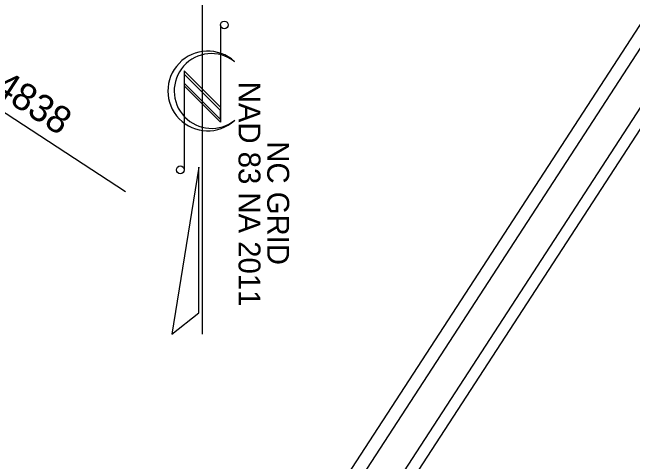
# Model space of a CAD drawing. Extents: x 2291197 to 2302790, y 592892 to 604246.
# Drawn here: x 2300199 to 2301153, y 599026 to 599716 of the extents above; entities that cross this region are included whole.
import ezdxf

# ---------------------------------------------------------------- set-up
doc = ezdxf.new("R2010")
doc.units = 0
for name, color, linetype in [('Prop Horizontal Alignment Station Label', 7, 'Continuous'), ('Sheet North Arrow CELL', 7, 'Continuous'), ('Sheet Plot Border Inside CELL', 7, 'Continuous'), ('Sheet Plot Border Outside CELL', 7, 'Continuous'), ('Sheet Title CELL', 7, 'Continuous')]:
    doc.layers.add(name, color=color, linetype=linetype)

msp = doc.modelspace()

# ---------------------------------------------------------------- linework, layer by layer
at = {"layer": 'Prop Horizontal Alignment Station Label'}
msp.add_line((2299671.29, 599897.36), (2300373.21, 599441.07), dxfattribs=at)
at = {"layer": 'Sheet North Arrow CELL'}
for p, q in [((2300491.59, 599221.54), (2300491.59, 599950.84)), ((2300519.07, 599697.05), (2300519.07, 599547.37)), ((2300539.72, 599641.28), (2300540.5, 599640.72)), ((2300519.07, 599570.71), (2300463.31, 599626.47)), ((2300463.31, 599626.47), (2300463.31, 599474.33)), ((2300519.07, 599565.21), (2300463.31, 599620.97)), ((2300463.31, 599620.97), (2300463.31, 599607.29)), ((2300519.07, 599551.52), (2300463.31, 599607.29)), ((2300463.31, 599607.29), (2300519.07, 599551.52)), ((2300519.07, 599547.37), (2300463.31, 599603.13)), ((2300519.07, 599551.52), (2300519.07, 599565.21))]:
    msp.add_line(p, q, dxfattribs=at)
msp.add_lwpolyline([(2300485.64, 599478.48), (2300444.35, 599221.54), (2300485.64, 599254.08)], close=True, dxfattribs=at)
for centre in [(2300525.02, 599696.93), (2300457.37, 599474.1)]:
    msp.add_circle(centre, 5.95, dxfattribs=at)
for centre, radius, start, end in [((2300499.34, 599595.31), 61.26, 47.84002, 312.39406), ((2300505.26, 599595.34), 57.43, 53.09504, 308.62871)]:
    msp.add_arc(centre, radius, start, end, dxfattribs=at)
at = {"layer": 'Sheet Plot Border Inside CELL'}
msp.add_lwpolyline([(2293886.07, 600604.03), (2299474.98, 596970.9), (2301775.2, 600509.37), (2296186.29, 604142.5)], close=True, dxfattribs=at)
at = {"layer": 'Sheet Plot Border Outside CELL'}
msp.add_lwpolyline([(2301839.23, 600574.85), (2296191.63, 604246.13), (2293793.55, 600557.12), (2299441.15, 596885.84)], close=True, dxfattribs=at)
at = {"layer": 'Sheet Title CELL'}
for points in [[(2299460.58, 597040.46), (2301706.05, 600494.71)], [(2299858.01, 597688.52), (2301678.41, 600488.89)]]:
    msp.add_lwpolyline(points, dxfattribs=at)

# ---------------------------------------------------------------- texts
at = {"layer": 'Prop Horizontal Alignment Station Label'}
msp.add_text('END TIP PROJECT B-4838', height=42, rotation=326.9737, dxfattribs=at).set_placement((2299688.48, 599905.45))
at = {"layer": 'Sheet North Arrow CELL'}
for s, p in [('NAD 83 NA 2011', (2300546.77, 599609.55)), ('NC GRID', (2300590.9, 599517.93))]:
    msp.add_text(s, height=33.66, rotation=270, dxfattribs=at).set_placement(p)

doc.saveas('drawing.dxf')
